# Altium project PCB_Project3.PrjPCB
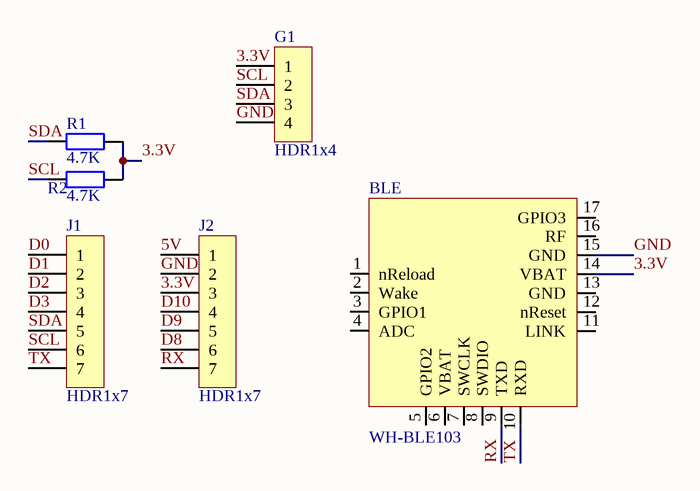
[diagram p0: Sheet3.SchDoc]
1 sheet, 6 parts. Net scope: global (net labels, ports and power ports of the same name join across sheets).
Board files: PCB3.PcbDoc, PCB3-1.PcbDoc, PCB3-2.PcbDoc

## Sheet Sheet3.SchDoc
size A4

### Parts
BLE  WH-BLE103  [PCBComponent_1]
G1  HDR1x4  [PIN-4-2.54-1.0]
J1  HDR1x7  [PIN-7-2.54-1.0]
J2  HDR1x7  [PIN-7-2.54-1.0]
R1  value 4.7K  [0603-1]  (hidden comment: Res1)
R2  value 4.7K  [0603-1]  (hidden comment: Res1)

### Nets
3.3V: BLE.14(VBAT) G1.1 J2.3 R1.2 R2.2
5V: J2.1
D0: J1.1
D1: J1.2
D2: J1.3
D3: J1.4
D8: J2.6
D9: J2.5
D10: J2.4
GND: BLE.15(GND) G1.4 J2.2
RX: BLE.9(TXD) J2.7
SCL: G1.2 J1.6 R2.1
SDA: G1.3 J1.5 R1.1
TX: BLE.10(RXD) J1.7

Not connected (* = marked no-connect by the designer): BLE 1(nReload) 2(Wake) 3(GPIO1) 4(ADC) 5(GPIO2) 6(VBAT) 7(SWCLK) 8(SWDIO) 11(LINK) 12(nReset) 13(GND) 16(RF) 17(GPIO3)

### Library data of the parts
G1 = HDR1x4: Connector
J1 J2 = HDR1x7: Connector
R1 R2 = Res1: 贴片电阻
